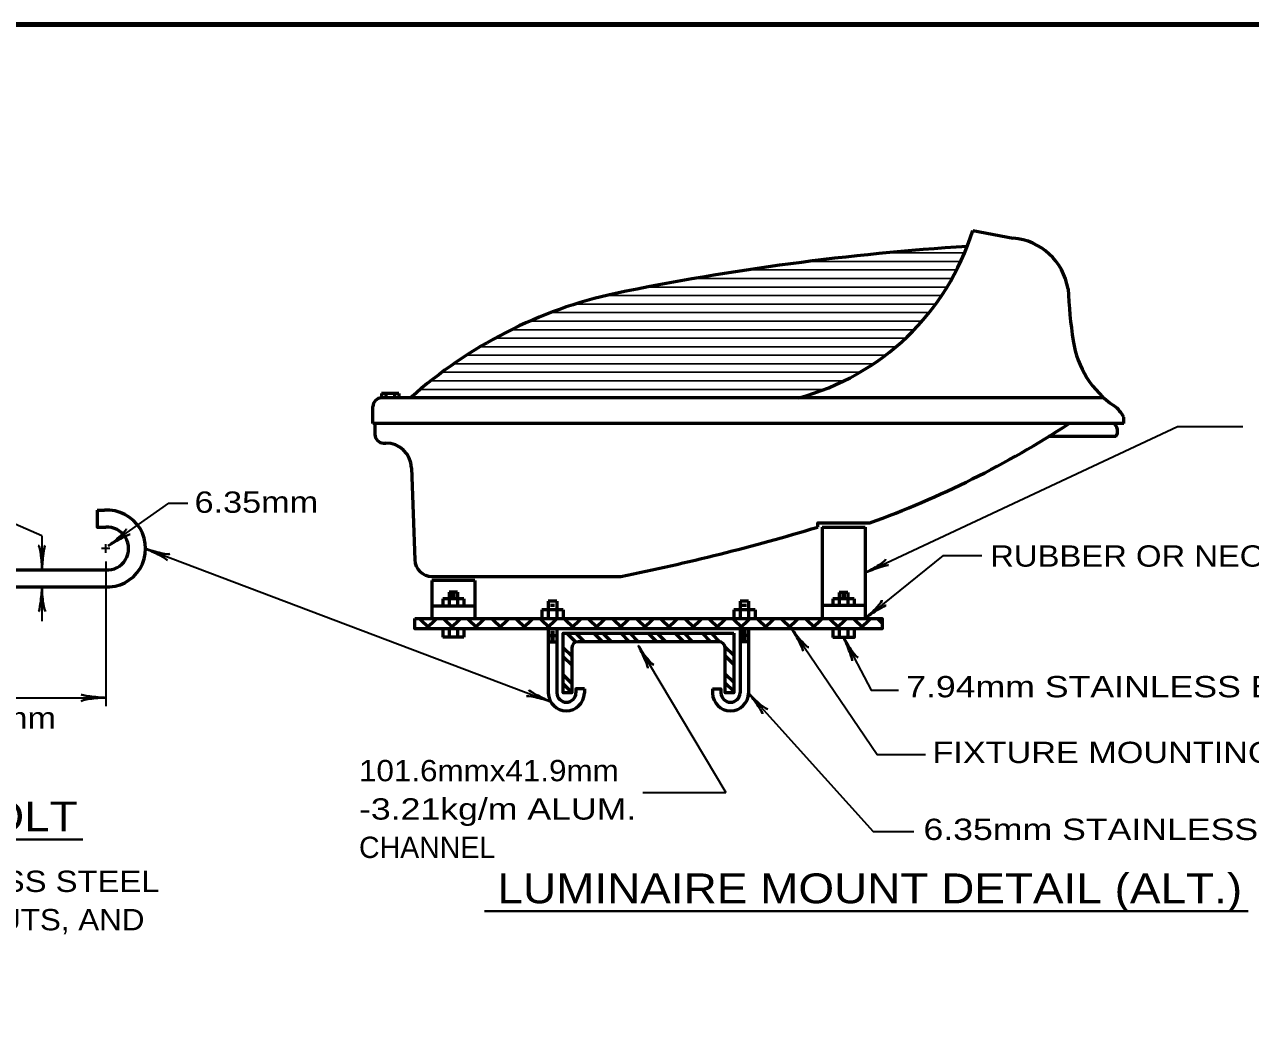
# Model space of a CAD drawing. Extents: x -94 to 762, y -50 to 494.
# Drawn here: x 432 to 604.6, y 347.6 to 487.4 of the extents above; entities that cross this region are included whole.
import ezdxf

# ---------------------------------------------------------------- set-up
doc = ezdxf.new("R2010")
doc.units = 0
doc.header["$LTSCALE"] = 1.2
doc.layers.add('1', color=7, linetype='Continuous', lineweight=53)

msp = doc.modelspace()

# ---------------------------------------------------------------- linework, layer by layer
at = {"layer": '1'}
for p, q in [((565.473, 458.379), (571.145, 457.301)), ((482.283, 435.419), (482.283, 434.819)), ((484.707, 435.419), (482.283, 435.419)), ((583.929, 434.819), (482.283, 434.819)), ((482.883, 435.419), (482.883, 434.819)), ((484.107, 435.419), (484.107, 434.819)), ((484.707, 435.419), (484.707, 434.819)), ((481.083, 431.195), (481.083, 433.595)), ((586.719, 431.195), (586.719, 432.095)), ((586.719, 431.195), (481.083, 431.195)), ((481.356, 431.195), (481.356, 429.659)), ((482.556, 428.459), (482.896, 428.459)), ((585.618, 429.371), (576.153, 429.371)), ((486.494, 424.989), (486.963, 412.019)), ((442.276, 419.01), (443.311, 419.01)), ((544.275, 416.624), (544.275, 403.787)), ((544.275, 416.624), (550.323, 416.624)), ((550.323, 416.624), (550.323, 403.787)), ((489.366, 409.13), (489.366, 403.826)), ((495.414, 409.13), (489.366, 409.13)), ((489.372, 409.691), (515.983, 409.691)), ((495.414, 409.13), (495.414, 403.826)), ((491.79, 407.453), (491.79, 405.506)), ((492.99, 407.453), (491.79, 407.453)), ((546.699, 407.413), (546.699, 405.611)), ((547.899, 407.413), (546.699, 407.413)), ((495.375, 405.486), (489.327, 405.486)), ((493.89, 406.553), (490.89, 406.553)), ((490.89, 406.553), (490.89, 405.506)), ((492.69, 407.002), (492.09, 407.002)), ((493.89, 406.553), (493.89, 405.506)), ((505.745, 406.187), (505.745, 404.987)), ((506.945, 406.187), (505.745, 406.187)), ((506.645, 405.587), (506.045, 405.587)), ((506.945, 406.187), (506.945, 404.987)), ((532.745, 406.187), (532.745, 404.987)), ((533.945, 406.187), (532.745, 406.187)), ((533.645, 405.587), (533.045, 405.587)), ((533.945, 406.187), (533.945, 404.987)), ((550.323, 405.611), (544.275, 405.611)), ((548.799, 406.514), (545.799, 406.514)), ((545.799, 406.514), (545.799, 405.611)), ((547.599, 406.964), (546.999, 406.964)), ((548.799, 406.514), (548.799, 405.611)), ((489.071, 402.287), (487.571, 403.787)), ((488.501, 402.287), (490.001, 403.787)), ((492.465, 402.287), (490.965, 403.787)), ((491.895, 402.287), (493.395, 403.787)), ((495.86, 402.287), (494.36, 403.787)), ((495.289, 402.287), (496.789, 403.787)), ((499.254, 402.287), (497.754, 403.787)), ((498.684, 402.287), (500.184, 403.787)), ((502.648, 402.287), (501.148, 403.787)), ((502.078, 402.287), (503.578, 403.787)), ((506.042, 402.287), (504.542, 403.787)), ((507.845, 404.987), (504.845, 404.987)), ((504.845, 404.987), (504.845, 403.787)), ((505.472, 402.287), (506.972, 403.787)), ((505.745, 404.987), (505.745, 403.787)), ((506.945, 404.987), (506.945, 403.787)), ((507.845, 404.987), (507.845, 403.787)), ((509.436, 402.287), (507.936, 403.787)), ((508.866, 402.287), (510.366, 403.787)), ((512.83, 402.287), (511.33, 403.787)), ((512.26, 402.287), (513.76, 403.787)), ((516.224, 402.287), (514.724, 403.787)), ((515.654, 402.287), (517.154, 403.787)), ((519.618, 402.287), (518.118, 403.787)), ((519.048, 402.287), (520.548, 403.787)), ((523.012, 402.287), (521.512, 403.787)), ((522.442, 402.287), (523.942, 403.787)), ((526.407, 402.287), (524.907, 403.787)), ((525.836, 402.287), (527.336, 403.787)), ((529.801, 402.287), (528.301, 403.787)), ((529.231, 402.287), (530.731, 403.787)), ((533.195, 402.287), (531.695, 403.787)), ((534.845, 404.987), (531.845, 404.987)), ((531.845, 404.987), (531.845, 403.787)), ((532.625, 402.287), (534.125, 403.787)), ((532.745, 404.987), (532.745, 403.787)), ((533.945, 404.987), (533.945, 403.787)), ((534.845, 404.987), (534.845, 403.787)), ((536.589, 402.287), (535.089, 403.787)), ((536.019, 402.287), (537.519, 403.787)), ((539.983, 402.287), (538.483, 403.787)), ((539.413, 402.287), (540.913, 403.787)), ((543.377, 402.287), (541.877, 403.787)), ((542.807, 402.287), (544.307, 403.787)), ((546.771, 402.287), (545.271, 403.787)), ((546.201, 402.287), (547.701, 403.787)), ((550.165, 402.287), (548.665, 403.787)), ((549.595, 402.287), (551.095, 403.787)), ((552.723, 403.123), (552.06, 403.787)), ((490.89, 402.326), (490.89, 401.126)), ((491.79, 402.326), (491.79, 401.126)), ((492.99, 402.326), (492.99, 401.126)), ((493.89, 402.326), (493.89, 401.126)), ((505.745, 402.287), (505.745, 393.243)), ((506.945, 402.287), (506.945, 393.287)), ((532.745, 402.287), (532.745, 393.287)), ((533.945, 402.287), (533.945, 393.243)), ((545.799, 402.287), (545.799, 401.087)), ((546.699, 402.287), (546.699, 401.087)), ((547.899, 402.287), (547.899, 401.087)), ((493.89, 401.126), (490.89, 401.126)), ((505.745, 401.387), (506.945, 401.387)), ((505.745, 400.487), (506.945, 400.487)), ((506.045, 401.837), (506.645, 401.837)), ((506.045, 400.937), (506.645, 400.937)), ((509.622, 400.418), (508.354, 401.687)), ((510.827, 400.487), (509.627, 401.687)), ((529.745, 400.487), (509.945, 400.487)), ((513.372, 400.487), (512.172, 401.687)), ((514.645, 400.487), (513.445, 401.687)), ((517.191, 400.487), (515.991, 401.687)), ((518.464, 400.487), (517.264, 401.687)), ((521.009, 400.487), (519.809, 401.687)), ((522.282, 400.487), (521.082, 401.687)), ((524.827, 400.487), (523.628, 401.687)), ((526.1, 400.487), (524.9, 401.687)), ((528.646, 400.487), (527.446, 401.687)), ((529.95, 400.456), (528.719, 401.687)), ((533.945, 401.387), (532.745, 401.387)), ((533.945, 400.487), (532.745, 400.487)), ((533.645, 401.837), (533.045, 401.837)), ((533.645, 400.937), (533.045, 400.937)), ((509.045, 398.45), (507.845, 399.65)), ((531.845, 398.561), (530.616, 399.79)), ((509.045, 397.178), (507.845, 398.377)), ((531.845, 397.288), (530.645, 398.488)), ((509.045, 394.632), (507.845, 395.832)), ((531.845, 394.742), (530.645, 395.942)), ((509.045, 393.359), (507.845, 394.559)), ((510.845, 393.887), (510.845, 393.243)), ((528.845, 393.887), (528.845, 393.243)), ((531.845, 393.469), (530.645, 394.669)), ((530.755, 393.287), (530.645, 393.397))]:
    msp.add_line(p, q, dxfattribs=at)
at = {"layer": '1', "lineweight": 25}
for p, q in [((563.798, 454.019), (542.385, 454.019)), ((564.326, 455.219), (553.152, 455.219)), ((563.215, 452.819), (533.739, 452.819)), ((561.872, 450.419), (519.714, 450.419)), ((562.575, 451.619), (526.315, 451.619)), ((561.103, 449.219), (513.716, 449.219)), ((559.345, 446.819), (506.082, 446.819)), ((560.263, 448.019), (509.531, 448.019)), ((558.34, 445.619), (503.152, 445.619)), ((557.239, 444.419), (500.576, 444.419)), ((554.691, 442.019), (496.163, 442.019)), ((556.028, 443.219), (498.266, 443.219)), ((553.202, 440.819), (494.231, 440.819)), ((549.615, 438.419), (490.773, 438.419)), ((551.527, 439.619), (492.441, 439.619)), ((547.377, 437.219), (489.213, 437.219)), ((544.642, 436.019), (487.747, 436.019))]:
    msp.add_line(p, q, dxfattribs=at)
at = {"layer": '1', "lineweight": 35}
for p, q in [((434.505, 415.41), (430.717, 417.026)), ((434.505, 415.41), (434.505, 410.61)), ((443.476, 413.01), (443.476, 414.21)), ((444.076, 413.61), (442.876, 413.61)), ((449.091, 413.61), (506.091, 392.051)), ((561.334, 412.619), (550.323, 403.787)), ((561.334, 412.619), (566.755, 412.619)), ((443.476, 411.81), (443.476, 391.41)), ((434.505, 408.21), (434.505, 403.41)), ((518.387, 399.965), (530.721, 379.279)), ((410.422, 392.61), (443.476, 392.61)), ((519.047, 379.279), (530.721, 379.279))]:
    msp.add_line(p, q, dxfattribs=at)
at = {"layer": '1', "lineweight": 40}
for p, q in [((415.621, 372.674), (440.27, 372.674)), ((496.753, 362.589), (604.23, 362.589))]:
    msp.add_line(p, q, dxfattribs=at)
at = {"layer": '1', "lineweight": 158}
msp.add_lwpolyline([(755.402, 487.372), (-36.298, 487.272), (-36.198, -38.728)], dxfattribs=at)
at = {"layer": '1', "lineweight": 35}
for points in [[(550.323, 410.205), (594.3, 430.775), (603.495, 430.775)], [(443.84, 413.995), (452.374, 420.013), (455.047, 420.013)], [(540.038, 402.287), (552.051, 384.629), (558.839, 384.629)], [(547.299, 401.087), (551.205, 393.674), (555.023, 393.674)], [(533.944, 393.243), (551.477, 373.782), (557.211, 373.782)]]:
    msp.add_lwpolyline(points, dxfattribs=at)
at = {"layer": '1'}
for points in [[(442.276, 419.01), (442.276, 416.61), (443.476, 416.61)], [(543.658, 416.624), (543.658, 417.224), (550.982, 417.224)], [(411.676, 410.61), (412.876, 410.61), (443.476, 410.61)], [(412.876, 408.21), (422.303, 408.21), (425.05, 408.21), (443.311, 408.21)], [(492.99, 407.453), (492.99, 406.553), (492.99, 405.506)], [(547.899, 407.413), (547.899, 406.514), (547.899, 405.611)], [(548.799, 402.287), (548.799, 401.087), (545.799, 401.087)], [(509.045, 399.587), (509.045, 393.287), (507.845, 393.287), (507.845, 401.687), (531.845, 401.687)], [(531.845, 401.687), (531.845, 393.287), (530.645, 393.287), (530.645, 399.587)], [(510.845, 393.887), (509.645, 393.887), (509.645, 393.287)], [(528.845, 393.887), (530.045, 393.887), (530.045, 393.287)]]:
    msp.add_lwpolyline(points, dxfattribs=at)
msp.add_lwpolyline([(486.966, 403.787), (552.723, 403.787), (552.723, 402.287), (486.966, 402.287)], close=True, dxfattribs=at)
for centre, radius, start, end in [((531.9, 468.772), 35.145, 284.92173, 342.79873), ((570.443, 448.764), 8.566, 9.49613, 85.29669), ((588.034, 93.351), 363.545, 93.67629, 101.55826), ((528.631, 387.574), 63.391, 102.2391, 131.80847), ((649.2, 453.44), 70.385, 182.6566, 188.67244), ((592.895, 444.806), 13.422, 188.48124, 235.98862), ((482.284, 433.603), 1.21, 90, 180), ((582.877, 430.221), 4.274, 25.9967, 54.02482), ((482.556, 429.659), 1.2, 180, 270), ((504.675, 545.341), 136.229, 289.87239, 303.081), ((584.577, 430.132), 1.29, 323.79969, 57.87712), ((482.896, 424.859), 3.6, 2.07218, 90), ((443.684, 413.61), 5.407, 266.04284, 93.95716), ((443.684, 413.61), 3.007, 266.04284, 93.95716), ((455.796, 708.846), 305.145, 281.3757, 286.73439), ((489.372, 412.115), 2.419, 182.00024, 270), ((509.945, 399.587), 0.9, 90, 180), ((529.745, 399.587), 0.9, 0, 90), ((508.295, 393.336), 2.551, 182.09574, 357.90426), ((508.295, 393.336), 1.351, 182.09574, 357.90426), ((531.395, 393.336), 2.551, 182.09574, 357.90426), ((531.395, 393.336), 1.351, 182.09574, 357.90426)]:
    msp.add_arc(centre, radius, start, end, dxfattribs=at)
at = {"layer": '1', "lineweight": 40}
for centre, major_axis, ratio, start_param, end_param in [((444.719, 415.021), (-1.643, -1.388), 0.122415, 0.8963533, 3.1415927), ((444.719, 415.021), (-1.643, -1.388), 0.122415, 0.8963533, 3.1415927), ((434.173, 411.92), (0.187, -2.143), 0.122415, 0.8963533, 3.1415927), ((434.759, 411.955), (-0.211, -2.108), 0.07063, 3.1407148, 5.41811), ((445.085, 414.563), (1.844, 1.042), 0.07063, 6.2823074, 8.5597026), ((445.085, 414.563), (1.844, 1.042), 0.07063, 6.2823074, 8.5597026), ((450.259, 412.897), (1.897, -0.943), 0.07063, 6.2823074, 8.5597026), ((450.259, 412.897), (1.897, -0.943), 0.07063, 6.2823074, 8.5597026), ((450.433, 413.457), (-2.071, 0.583), 0.122415, 0.8963533, 3.1415927), ((450.433, 413.457), (-2.071, 0.583), 0.122415, 0.8963533, 3.1415927), ((551.369, 411.06), (-1.862, -1.078), 0.122415, 0.8963533, 3.1415927), ((551.649, 410.545), (-1.999, -0.702), 0.07063, 3.1407148, 5.41811), ((434.251, 406.866), (0.211, 2.108), 0.07063, 3.1407148, 5.41811), ((434.836, 406.901), (-0.187, 2.143), 0.122415, 0.8963533, 3.1415927), ((551.137, 404.865), (-1.554, -1.487), 0.122415, 0.8963533, 3.1415927), ((551.531, 404.43), (1.776, 1.155), 0.07063, 6.2823074, 8.5597026), ((540.584, 401.032), (1.011, -1.861), 0.07063, 6.2823074, 8.5597026), ((540.584, 401.032), (1.011, -1.861), 0.07063, 6.2823074, 8.5597026), ((541.048, 401.39), (-1.36, 1.666), 0.122415, 0.8963533, 3.1415927), ((541.048, 401.39), (-1.36, 1.666), 0.122415, 0.8963533, 3.1415927), ((547.701, 399.779), (0.796, -1.963), 0.07063, 6.2823074, 8.5597026), ((547.701, 399.779), (0.796, -1.963), 0.07063, 6.2823074, 8.5597026), ((548.203, 400.083), (-1.165, 1.808), 0.122415, 0.8963533, 3.1415927), ((548.203, 400.083), (-1.165, 1.808), 0.122415, 0.8963533, 3.1415927), ((518.857, 398.68), (-0.898, 1.918), 0.07063, 3.1407148, 5.41811), ((518.857, 398.68), (-0.898, 1.918), 0.07063, 3.1407148, 5.41811), ((519.342, 399.01), (-1.258, 1.745), 0.122415, 0.8963533, 3.1415927), ((519.342, 399.01), (-1.258, 1.745), 0.122415, 0.8963533, 3.1415927), ((504.923, 392.764), (1.897, -0.943), 0.07063, 3.1407148, 5.41811), ((442.167, 392.279), (2.143, 0.187), 0.122415, 0.8963533, 3.1415927), ((442.132, 392.864), (2.108, -0.211), 0.07063, 3.1407148, 5.41811), ((504.749, 392.204), (2.071, -0.583), 0.122415, 0.8963533, 3.1415927), ((534.655, 392.074), (1.254, -1.707), 0.07063, 6.2823074, 8.5597026), ((535.067, 392.492), (-1.574, 1.467), 0.122415, 0.8963533, 3.1415927)]:
    msp.add_ellipse(centre, major_axis=major_axis, ratio=ratio, start_param=start_param, end_param=end_param, dxfattribs=at)

# ---------------------------------------------------------------- texts
at = {"layer": '1'}
for s, height, width, p in [('6.35mm', 3, 1.2, (455.977, 418.644)), ('RUBBER OR NEOPRENE PAD', 3, 1.15, (567.941, 411.062)), ('7.94mm STAINLESS BOLTS FOUR (4) PER PLATE', 3, 1.25, (556.113, 392.671)), ('73.03mm', 3, 1.2, (416.415, 388.266)), ('FIXTURE MOUNTING PLATE 6.35mm THICK ALUMINUM', 3, 1.2, (559.808, 383.416)), ('101.6mmx41.9mm', 3, 1.1, (479.12, 380.857)), ('J-BOLT', 4.2, 1.15, (417.287, 373.805)), ('-3.21kg/m ALUM.', 3, 1.25, (479.12, 375.457)), ('6.35mm STAINLESS J BOLT (4 PER PLATE) (NO TRIPLE NUT)', 3, 1.25, (558.545, 372.587)), ('(STAINLESS STEEL', 3, 1.15, (408.23, 365.273)), ('LUMINAIRE MOUNT DETAIL (ALT.)', 4.2, 1.15, (498.599, 363.679)), ('BOLTS, NUTS, AND', 3, 1.1, (408.23, 359.873))]:
    msp.add_text(s, height=height, dxfattribs=dict(at, width=width)).set_placement(p)
msp.add_text('CHANNEL', height=3, dxfattribs=at).set_placement((479.12, 370.057))

doc.saveas('drawing.dxf')
